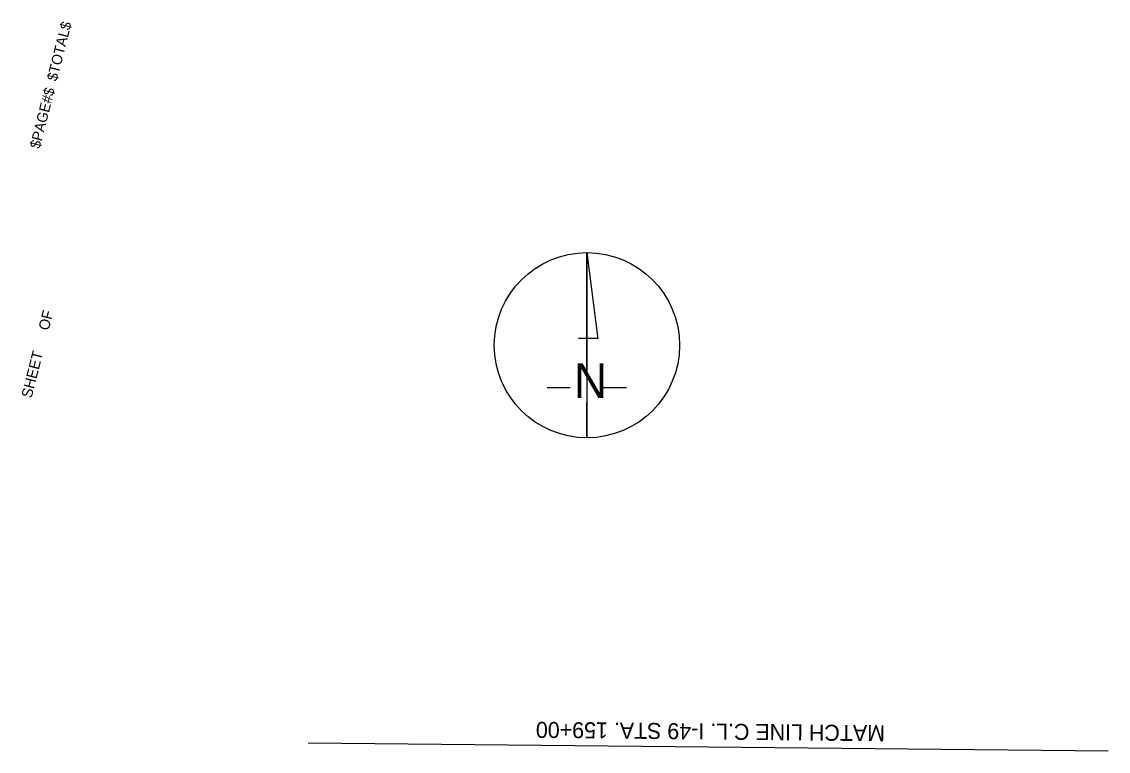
# Model space of a CAD drawing. Extents: x 631240 to 632720, y 370244 to 373550.
import ezdxf

# ---------------------------------------------------------------- set-up
doc = ezdxf.new("R2010")
doc.units = 0
for name, color, linetype in [('Copy of R_Dimension', 7, 'Continuous'), ('GN_Dimension', 7, 'Continuous'), ('R_Draft', 7, 'Continuous'), ('S_DITCHLINE', 7, 'Continuous')]:
    doc.layers.add(name, color=color, linetype=linetype)

msp = doc.modelspace()

# ---------------------------------------------------------------- linework, layer by layer
at = {"layer": 'Copy of R_Dimension'}
msp.add_line((632070.9, 373289.9), (632070.9, 373081.6), dxfattribs=at)
msp.add_circle((632070.9, 373185.7), 104.2, dxfattribs=at)
at = {"layer": 'GN_Dimension'}
for p, q in [((632070.9, 373289.9), (632083, 373192.9)), ((632070.9, 373154.3), (632070.9, 373289.9)), ((632061.5, 373193.6), (632083, 373193.6)), ((632026.3, 373138.3), (632052, 373138.3)), ((632088, 373138.3), (632115.5, 373138.3)), ((632070.9, 373081.6), (632070.9, 373121.4))]:
    msp.add_line(p, q, dxfattribs=at)
at = {"layer": 'R_Draft'}
msp.add_line((632657.2, 372728.8), (631757.3, 372737.8), dxfattribs=at)

# ---------------------------------------------------------------- texts
at = {"layer": 'Copy of R_Dimension'}
for s, p in [('OF', (631465.4, 373201.6)), ('SHEET', (631446.2, 373125.5))]:
    msp.add_text(s, height=12, rotation=75.7827, dxfattribs=at).set_placement(p)
at = {"layer": 'GN_Dimension'}
msp.add_text('N', height=38.8, dxfattribs=at).set_placement((632056.2, 373126.4))
at = {"layer": 'R_Draft'}
for s, p in [('$TOTAL$', (631474.6, 373482.1)), ('$PAGE#$', (631455.4, 373406.2))]:
    msp.add_text(s, height=11.72, rotation=75.7827, dxfattribs=at).set_placement(p)
at = {"layer": 'S_DITCHLINE'}
msp.add_text('MATCH LINE C.L. I-49 STA. 159+00', height=18, rotation=179.4304, dxfattribs=at).set_placement((632406.2, 372758.1))

doc.saveas('drawing.dxf')
